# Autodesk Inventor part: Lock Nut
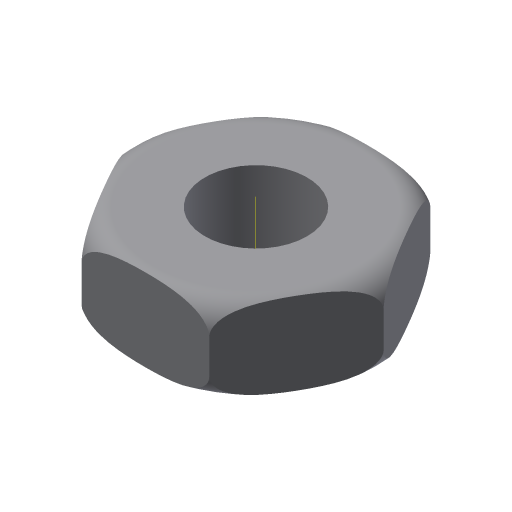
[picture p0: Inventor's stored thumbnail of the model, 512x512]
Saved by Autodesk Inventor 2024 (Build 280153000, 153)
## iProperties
Created: 2009-04
Part Number: Lock Nut
Document SubType Name: Modeling
Designer: Sham
Density: 1 g/cm^3
Material: Generic
Appearance: Default
Author: Sham
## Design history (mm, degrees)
sketch "Sketch1"
  geometry: L1 (7.5, 12.99)-(15, 0); L2 (15, 0)-(7.5, -12.99); L3 (7.5, -12.99)-(-7.5, -12.99); L4 (-7.5, -12.99)-(-15, 0); L5 (-15, 0)-(-7.5, 12.99); L6 (-7.5, 12.99)-(7.5, 12.99); C1 r 6 at (0, 0); 1 further point
  constraints: 12 end point, 1 centre point, 1 coincident, 13 other
  dimensions: "d0" = 30 distance of L1.end L4.end; "d1" = 12 diameter of C1
extrude "Extrusion1" new body sketch "Sketch1" distance "d2" = 10; taper "d3" = 0 deg
sketch "Sketch2"
  geometry: L1 (-12, 0)-(-12, -0.022); L2 (-15, 7)-(-15, 3); L3 (0, -2.87)-(0, 12.87) reference; A1 r 3 centre (-12, 7) between (-12, 10) and (-15, 7); A2 r 3 centre (-12, 3) between (-15, 3) and (-12, 0)
  constraints: 4 end point, 4 point on circle, 2 centre point, 1 tangent
revolve "Revolution1" sketch "Sketch2" stored, may be unused: angle "d7" = 90 deg
body "Solid1"
other parameters: "d6" = 90 deg
